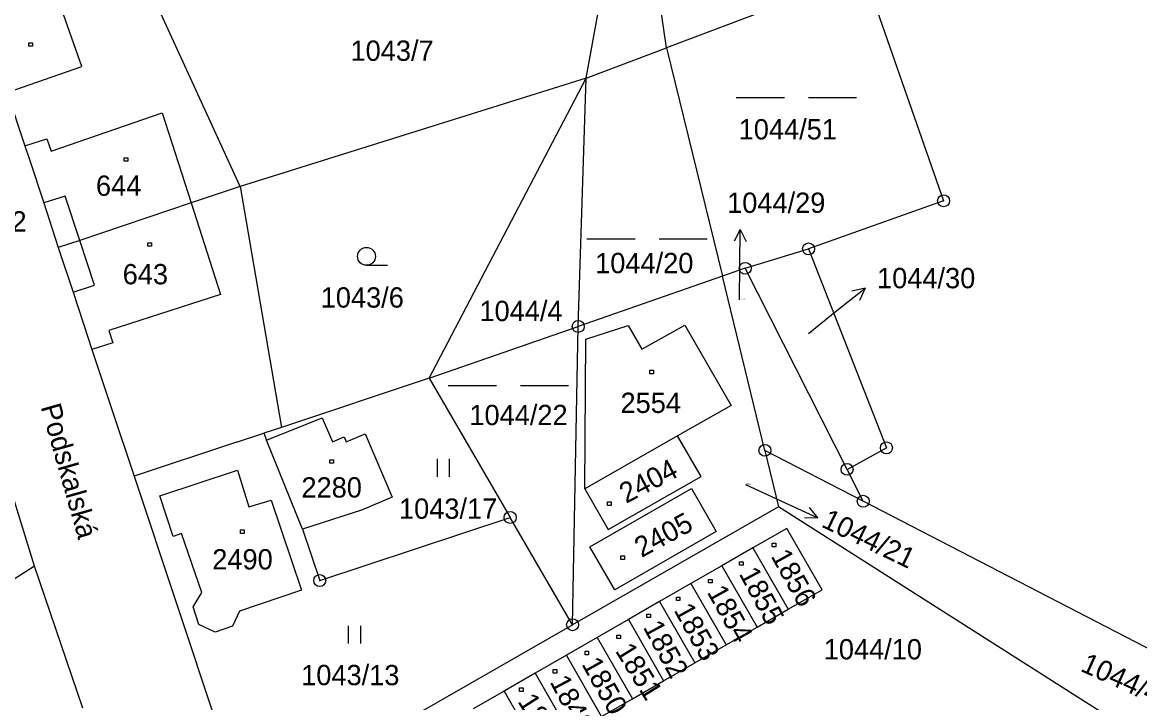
# Model space of a CAD drawing. Extents: x -795483 to -789093, y -1112258 to -1108741.
# Drawn here: x -792126 to -792032.5, y -1109594.4 to -1109537.4 of the extents above; entities that cross this region are included whole.
import ezdxf

# ---------------------------------------------------------------- set-up
doc = ezdxf.new("R2010")
doc.units = 0
for name, color, linetype in [('Komunikace', 7, 'Continuous'), ('Vrstva 1', 7, 'Continuous'), ('Vrstva 14', 7, 'Continuous'), ('Vrstva 15', 7, 'Continuous'), ('Vrstva 16', 7, 'Continuous'), ('Vrstva 2', 7, 'Continuous'), ('Vrstva 23', 7, 'Continuous'), ('Vrstva 25', 7, 'Continuous'), ('Vrstva 28', 7, 'Continuous'), ('Vrstva 38', 7, 'Continuous')]:
    doc.layers.add(name, color=color, linetype=linetype)

msp = doc.modelspace()

# ---------------------------------------------------------------- linework, layer by layer
at = {"layer": 'Komunikace'}
for p, q in [((-792066, -1109560.63), (-792065.97, -1109557.74)), ((-792060.24, -1109563.45), (-792057.85, -1109561.54)), ((-792065.51, -1109576.1), (-792062.18, -1109577.64))]:
    msp.add_line(p, q, dxfattribs=at)
at = {"layer": 'Vrstva 1'}
for p, q in [((-792072.1, -1109539.55), (-792075, -1109519.53)), ((-792078.82, -1109542.08), (-792076.76, -1109530.55)), ((-792107.79, -1109551.14), (-792116.17, -1109532.79)), ((-792055.59, -1109533.29), (-792072.1, -1109539.55)), ((-792055.59, -1109533.29), (-792048.93, -1109552.35)), ((-792078.82, -1109542.08), (-792072.1, -1109539.55)), ((-792072.1, -1109539.55), (-792067.42, -1109558.66)), ((-792078.82, -1109542.08), (-792107.79, -1109551.14)), ((-792091.96, -1109567.21), (-792078.82, -1109542.08)), ((-792079.5, -1109562.87), (-792078.82, -1109542.08)), ((-792127.27, -1109543.27), (-792125.78, -1109547.74)), ((-792125.78, -1109547.74), (-792125.42, -1109548.82)), ((-792125.42, -1109548.82), (-792124.19, -1109552.52)), ((-792107.79, -1109551.14), (-792111.88, -1109552.53)), ((-792107.79, -1109551.14), (-792104.33, -1109571.32)), ((-792048.93, -1109552.35), (-792060.23, -1109556.38)), ((-792124.19, -1109552.52), (-792123, -1109556.27)), ((-792111.88, -1109552.53), (-792121.19, -1109555.68)), ((-792121.19, -1109555.68), (-792123, -1109556.27)), ((-792123, -1109556.27), (-792121.74, -1109560)), ((-792065.53, -1109558), (-792060.23, -1109556.38)), ((-792060.23, -1109556.38), (-792053.71, -1109573.03)), ((-792065.53, -1109558), (-792067.42, -1109558.66)), ((-792057.01, -1109574.83), (-792065.53, -1109558)), ((-792067.42, -1109558.66), (-792079.5, -1109562.87)), ((-792063.88, -1109573.24), (-792067.42, -1109558.66)), ((-792121.74, -1109560), (-792120.53, -1109563.77)), ((-792091.96, -1109567.21), (-792079.5, -1109562.87)), ((-792079.97, -1109587.84), (-792079.5, -1109562.87)), ((-792078.85, -1109563.94), (-792075.31, -1109562.78)), ((-792075.31, -1109562.78), (-792074.18, -1109564.78)), ((-792074.18, -1109564.78), (-792070.57, -1109562.75)), ((-792070.57, -1109562.75), (-792066.71, -1109569.49)), ((-792120.53, -1109563.77), (-792120.18, -1109564.81)), ((-792078.94, -1109576.46), (-792078.85, -1109563.94)), ((-792120.18, -1109564.81), (-792118.56, -1109569.65)), ((-792091.96, -1109567.21), (-792104.33, -1109571.32)), ((-792091.96, -1109567.21), (-792085.19, -1109578.86)), ((-792118.56, -1109569.65), (-792116.64, -1109575.4)), ((-792066.71, -1109569.49), (-792071.18, -1109572.02)), ((-792105.57, -1109572.4), (-792100.91, -1109570.51)), ((-792100.91, -1109570.51), (-792100.05, -1109572.52)), ((-792108.07, -1109572.56), (-792105.81, -1109571.81)), ((-792104.33, -1109571.32), (-792105.81, -1109571.81)), ((-792105.81, -1109571.81), (-792105.57, -1109572.4)), ((-792098.92, -1109572.53), (-792097.31, -1109571.85)), ((-792097.31, -1109571.85), (-792095.07, -1109577.16)), ((-792071.18, -1109572.02), (-792078.94, -1109576.46)), ((-792069.22, -1109575.42), (-792071.18, -1109572.02)), ((-792108.07, -1109572.56), (-792116.64, -1109575.4)), ((-792102.57, -1109579.83), (-792105.57, -1109572.4)), ((-792100.05, -1109572.52), (-792099.09, -1109572.12)), ((-792099.09, -1109572.12), (-792098.92, -1109572.53)), ((-792124.98, -1109582.94), (-792128, -1109573.23)), ((-792063.88, -1109573.24), (-792062.74, -1109577.96)), ((-792055.66, -1109577.5), (-792063.88, -1109573.24)), ((-792057.01, -1109574.83), (-792053.71, -1109573.03)), ((-792055.66, -1109577.5), (-792057.01, -1109574.83)), ((-792116.64, -1109575.4), (-792107.29, -1109603.5)), ((-792114.5, -1109577.06), (-792107.99, -1109574.91)), ((-792107.99, -1109574.91), (-792107.04, -1109577.96)), ((-792076.99, -1109579.86), (-792069.22, -1109575.42)), ((-792078.94, -1109576.46), (-792076.99, -1109579.86)), ((-792078.52, -1109581.31), (-792070.03, -1109576.44)), ((-792070.03, -1109576.44), (-792067.96, -1109580.04)), ((-792113.38, -1109580.46), (-792114.5, -1109577.06)), ((-792107.04, -1109577.96), (-792105.17, -1109577.4)), ((-792105.17, -1109577.4), (-792102.66, -1109584.95)), ((-792095.07, -1109577.16), (-792097.63, -1109578.24)), ((-792019.39, -1109596.27), (-792055.66, -1109577.5)), ((-792097.63, -1109578.24), (-792102.57, -1109579.83)), ((-792062.74, -1109577.96), (-792079.97, -1109587.84)), ((-792030.22, -1109598.67), (-792062.74, -1109577.96)), ((-792101.12, -1109584.14), (-792085.19, -1109578.86)), ((-792079.97, -1109587.84), (-792085.19, -1109578.86)), ((-792112.69, -1109580.19), (-792113.38, -1109580.46)), ((-792110.99, -1109585.13), (-792112.69, -1109580.19)), ((-792102.57, -1109579.83), (-792101.12, -1109584.14)), ((-792067.96, -1109580.04), (-792076.44, -1109584.92)), ((-792062.04, -1109579.77), (-792064.88, -1109581.41)), ((-792059.09, -1109584.91), (-792062.04, -1109579.77)), ((-792076.44, -1109584.92), (-792078.52, -1109581.31)), ((-792064.88, -1109581.41), (-792067.48, -1109582.9)), ((-792064.88, -1109581.41), (-792061.93, -1109586.54)), ((-792124.98, -1109582.94), (-792150.58, -1109599.21)), ((-792120.93, -1109594.82), (-792124.98, -1109582.94)), ((-792067.48, -1109582.9), (-792070.09, -1109584.4)), ((-792067.48, -1109582.9), (-792064.53, -1109588.04)), ((-792111.72, -1109586.33), (-792110.99, -1109585.13)), ((-792102.66, -1109584.95), (-792107.82, -1109586.71)), ((-792070.09, -1109584.4), (-792072.69, -1109585.9)), ((-792070.09, -1109584.4), (-792067.13, -1109589.53)), ((-792061.93, -1109586.54), (-792059.09, -1109584.91)), ((-792072.69, -1109585.9), (-792075.29, -1109587.41)), ((-792072.69, -1109585.9), (-792069.74, -1109591.04)), ((-792111.24, -1109587.81), (-792111.72, -1109586.33)), ((-792107.82, -1109586.71), (-792108.43, -1109587.95)), ((-792064.53, -1109588.04), (-792061.93, -1109586.54)), ((-792109.88, -1109588.45), (-792111.24, -1109587.81)), ((-792108.43, -1109587.95), (-792109.88, -1109588.45)), ((-792095.51, -1109596.74), (-792079.97, -1109587.84)), ((-792075.29, -1109587.41), (-792077.9, -1109588.9)), ((-792075.29, -1109587.41), (-792072.35, -1109592.53)), ((-792077.9, -1109588.9), (-792080.49, -1109590.4)), ((-792077.9, -1109588.9), (-792074.95, -1109594.03)), ((-792067.13, -1109589.53), (-792064.53, -1109588.04)), ((-792069.74, -1109591.04), (-792067.13, -1109589.53)), ((-792080.49, -1109590.4), (-792083.09, -1109591.89)), ((-792077.54, -1109595.52), (-792080.49, -1109590.4)), ((-792072.35, -1109592.53), (-792069.74, -1109591.04)), ((-792083.09, -1109591.89), (-792085.7, -1109593.39)), ((-792083.09, -1109591.89), (-792080.14, -1109597.02)), ((-792074.95, -1109594.03), (-792072.35, -1109592.53)), ((-792085.7, -1109593.39), (-792088.29, -1109594.89)), ((-792085.7, -1109593.39), (-792082.75, -1109598.52)), ((-792077.54, -1109595.52), (-792074.95, -1109594.03))]:
    msp.add_line(p, q, dxfattribs=at)
at = {"layer": 'Vrstva 16'}
for p, q in [((-792065.939, -1109554.74), (-792066.449, -1109555.735)), ((-792065.97, -1109557.74), (-792065.939, -1109554.74)), ((-792065.939, -1109554.74), (-792065.449, -1109555.745)), ((-792057.85, -1109561.54), (-792055.504, -1109559.669)), ((-792055.504, -1109559.669), (-792056.598, -1109559.902)), ((-792055.504, -1109559.669), (-792055.974, -1109560.683)), ((-792062.18, -1109577.64), (-792059.454, -1109578.894)), ((-792059.454, -1109578.894), (-792060.154, -1109578.022)), ((-792059.454, -1109578.894), (-792060.572, -1109578.93))]:
    msp.add_line(p, q, dxfattribs=at)
at = {"layer": 'Vrstva 2'}
for p, q in [((-792121.03, -1109541.11), (-792123.11, -1109535.18)), ((-792127.27, -1109543.27), (-792121.03, -1109541.11)), ((-792123.6, -1109548.19), (-792114.3, -1109544.99)), ((-792114.3, -1109544.99), (-792111.88, -1109552.53)), ((-792125.78, -1109547.74), (-792123.96, -1109547.16)), ((-792123.96, -1109547.16), (-792123.6, -1109548.19)), ((-792122.41, -1109551.96), (-792124.19, -1109552.52)), ((-792121.19, -1109555.68), (-792122.41, -1109551.96)), ((-792111.88, -1109552.53), (-792109.42, -1109560.18)), ((-792119.97, -1109559.4), (-792121.19, -1109555.68)), ((-792121.74, -1109560), (-792119.97, -1109559.4)), ((-792109.42, -1109560.18), (-792118.76, -1109563.2)), ((-792118.76, -1109563.2), (-792118.43, -1109564.23)), ((-792118.43, -1109564.23), (-792120.18, -1109564.81))]:
    msp.add_line(p, q, dxfattribs=at)
at = {"layer": 'Vrstva 23'}
for p, q in [((-792066.275, -1109543.7), (-792062.255, -1109543.7)), ((-792060.245, -1109543.7), (-792056.225, -1109543.7)), ((-792078.765, -1109555.52), (-792074.745, -1109555.52)), ((-792072.735, -1109555.52), (-792068.715, -1109555.52)), ((-792097.21, -1109557.75), (-792095.46, -1109557.75)), ((-792090.365, -1109567.8), (-792086.345, -1109567.8)), ((-792084.335, -1109567.8), (-792080.315, -1109567.8)), ((-792091.28, -1109575.46), (-792091.28, -1109573.96)), ((-792090.28, -1109573.96), (-792090.28, -1109575.46)), ((-792098.71, -1109589.42), (-792098.71, -1109587.92)), ((-792097.71, -1109587.92), (-792097.71, -1109589.42))]:
    msp.add_line(p, q, dxfattribs=at)
msp.add_circle((-792097.21, -1109557), 0.75, dxfattribs=at)
at = {"layer": 'Vrstva 25'}
for p, q in [((-792125.45, -1109539.11), (-792125.15, -1109539.11)), ((-792125.45, -1109539.41), (-792125.45, -1109539.11)), ((-792125.15, -1109539.11), (-792125.15, -1109539.41)), ((-792125.15, -1109539.41), (-792125.45, -1109539.41)), ((-792117.47, -1109548.74), (-792117.17, -1109548.74)), ((-792117.47, -1109549.04), (-792117.47, -1109548.74)), ((-792117.17, -1109549.04), (-792117.47, -1109549.04)), ((-792117.17, -1109548.74), (-792117.17, -1109549.04)), ((-792115.49, -1109555.86), (-792115.19, -1109555.86)), ((-792115.49, -1109556.16), (-792115.49, -1109555.86)), ((-792115.19, -1109556.16), (-792115.49, -1109556.16)), ((-792115.19, -1109555.86), (-792115.19, -1109556.16)), ((-792073.5, -1109566.54), (-792073.2, -1109566.54)), ((-792073.5, -1109566.84), (-792073.5, -1109566.54)), ((-792073.2, -1109566.84), (-792073.5, -1109566.84)), ((-792073.2, -1109566.54), (-792073.2, -1109566.84)), ((-792100.28, -1109574.02), (-792099.98, -1109574.02)), ((-792100.28, -1109574.32), (-792100.28, -1109574.02)), ((-792099.98, -1109574.32), (-792100.28, -1109574.32)), ((-792099.98, -1109574.02), (-792099.98, -1109574.32)), ((-792077.05, -1109577.55), (-792076.75, -1109577.55)), ((-792077.05, -1109577.85), (-792077.05, -1109577.55)), ((-792076.75, -1109577.55), (-792076.75, -1109577.85)), ((-792076.75, -1109577.85), (-792077.05, -1109577.85)), ((-792107.74, -1109579.9), (-792107.44, -1109579.9)), ((-792107.74, -1109580.2), (-792107.74, -1109579.9)), ((-792107.44, -1109580.2), (-792107.74, -1109580.2)), ((-792107.44, -1109579.9), (-792107.44, -1109580.2)), ((-792063.28, -1109581.02), (-792062.98, -1109581.02)), ((-792063.28, -1109581.32), (-792063.28, -1109581.02)), ((-792062.98, -1109581.32), (-792063.28, -1109581.32)), ((-792062.98, -1109581.02), (-792062.98, -1109581.32)), ((-792075.94, -1109582.08), (-792075.64, -1109582.08)), ((-792075.94, -1109582.38), (-792075.94, -1109582.08)), ((-792075.64, -1109582.08), (-792075.64, -1109582.38)), ((-792075.64, -1109582.38), (-792075.94, -1109582.38)), ((-792066, -1109582.56), (-792065.7, -1109582.56)), ((-792066, -1109582.86), (-792066, -1109582.56)), ((-792065.7, -1109582.86), (-792066, -1109582.86)), ((-792065.7, -1109582.56), (-792065.7, -1109582.86)), ((-792068.59, -1109584.04), (-792068.29, -1109584.04)), ((-792068.59, -1109584.34), (-792068.59, -1109584.04)), ((-792068.29, -1109584.04), (-792068.29, -1109584.34)), ((-792068.29, -1109584.34), (-792068.59, -1109584.34)), ((-792071.29, -1109585.52), (-792070.99, -1109585.52)), ((-792071.29, -1109585.82), (-792071.29, -1109585.52)), ((-792070.99, -1109585.82), (-792071.29, -1109585.82)), ((-792070.99, -1109585.52), (-792070.99, -1109585.82)), ((-792073.75, -1109586.94), (-792073.45, -1109586.94)), ((-792073.75, -1109587.24), (-792073.75, -1109586.94)), ((-792073.45, -1109586.94), (-792073.45, -1109587.24)), ((-792073.45, -1109587.24), (-792073.75, -1109587.24)), ((-792076.26, -1109588.7), (-792075.96, -1109588.7)), ((-792076.26, -1109589), (-792076.26, -1109588.7)), ((-792075.96, -1109588.7), (-792075.96, -1109589)), ((-792075.96, -1109589), (-792076.26, -1109589)), ((-792078.93, -1109590.06), (-792078.63, -1109590.06)), ((-792078.93, -1109590.36), (-792078.93, -1109590.06)), ((-792078.63, -1109590.36), (-792078.93, -1109590.36)), ((-792078.63, -1109590.06), (-792078.63, -1109590.36)), ((-792081.59, -1109591.59), (-792081.29, -1109591.59)), ((-792081.59, -1109591.89), (-792081.59, -1109591.59)), ((-792081.29, -1109591.59), (-792081.29, -1109591.89)), ((-792081.29, -1109591.89), (-792081.59, -1109591.89)), ((-792084.4, -1109593.13), (-792084.1, -1109593.13)), ((-792084.4, -1109593.43), (-792084.4, -1109593.13)), ((-792084.1, -1109593.43), (-792084.4, -1109593.43)), ((-792084.1, -1109593.13), (-792084.1, -1109593.43))]:
    msp.add_line(p, q, dxfattribs=at)
at = {"layer": 'Vrstva 28'}
for centre, radius in [((-792048.93, -1109552.35), 0.5), ((-792048.93, -1109552.35), 0.01), ((-792060.23, -1109556.38), 0.5), ((-792060.23, -1109556.38), 0.01), ((-792065.53, -1109558), 0.5), ((-792065.53, -1109558), 0.01), ((-792079.5, -1109562.87), 0.5), ((-792079.5, -1109562.87), 0.01), ((-792063.88, -1109573.24), 0.5), ((-792053.71, -1109573.03), 0.5), ((-792063.88, -1109573.24), 0.01), ((-792053.71, -1109573.03), 0.01), ((-792057.01, -1109574.83), 0.5), ((-792057.01, -1109574.83), 0.01), ((-792055.66, -1109577.5), 0.5), ((-792055.66, -1109577.5), 0.01), ((-792085.19, -1109578.86), 0.5), ((-792085.19, -1109578.86), 0.01), ((-792101.12, -1109584.14), 0.5), ((-792101.12, -1109584.14), 0.01), ((-792079.97, -1109587.84), 0.5), ((-792079.97, -1109587.84), 0.01)]:
    msp.add_circle(centre, radius, dxfattribs=at)

# ---------------------------------------------------------------- texts
at = {"layer": 'Vrstva 14'}
for s, height, p in [('1043/7', 1.7, (-792098.545, -1109540.63)), ('1044/51', 1.7, (-792066.073, -1109547.21)), ('1043/12', 1.7, (-792133.861, -1109554.92)), ('1044/20', 1.7, (-792078.08, -1109558.41)), ('1043/6', 1.7, (-792101.038, -1109561.29)), ('1044/4', 1.7, (-792087.76, -1109562.42)), ('1044/29', 0.1, (-792066, -1109560.63)), ('1044/30', 0.1, (-792060.24, -1109563.45)), ('1044/22', 1.7, (-792088.6, -1109571.13)), ('1044/21', 0.1, (-792065.51, -1109576.1)), ('1043/17', 1.7, (-792094.49, -1109578.97)), ('1044/10', 1.7, (-792058.96, -1109590.74)), ('1043/13', 1.7, (-792102.671, -1109592.9))]:
    msp.add_text(s, height=height, dxfattribs=at).set_placement(p)
msp.add_text('1044/45', height=1.7, rotation=335.7, dxfattribs=at).set_placement((-792037.566, -1109591.68))
at = {"layer": 'Vrstva 15'}
for s, p in [('644', (-792119.838, -1109551.93)), ('643', (-792117.603, -1109559.34)), ('2554', (-792075.96, -1109570.11)), ('2280', (-792102.65, -1109577.19)), ('2490', (-792110.11, -1109583.21))]:
    msp.add_text(s, height=1.7, dxfattribs=at).set_placement(p)
for s, rotation, p in [('2404', 27.62343, (-792075.49, -1109577.72)), ('2405', 28.30752, (-792074.2, -1109582.25)), ('1856', 299.10897, (-792063.42, -1109582.09)), ('1855', 298.26855, (-792066.08, -1109583.57)), ('1854', 299.23281, (-792068.76, -1109585.11)), ('1853', 299.14974, (-792071.54, -1109586.61)), ('1852', 298.46808, (-792074.11, -1109588.04)), ('1851', 301.75245, (-792076.45, -1109590.02)), ('1850', 299.19753, (-792079.25, -1109591.13)), ('1849', 297.99414, (-792081.91, -1109592.61)), ('1848', 302.45922, (-792084.61, -1109594.26))]:
    msp.add_text(s, height=1.7, rotation=rotation, dxfattribs=at).set_placement(p)
at = {"layer": 'Vrstva 16'}
for s, p in [('1044/29', (-792067.04, -1109553.36)), ('1044/30', (-792054.5, -1109559.67))]:
    msp.add_text(s, height=1.7, dxfattribs=at).set_placement(p)
msp.add_text('1044/21', height=1.7, rotation=334.15965, dxfattribs=at).set_placement((-792059.24, -1109579.6))
at = {"layer": 'Vrstva 38'}
msp.add_text('Podskalská', height=1.7, rotation=285.86493, dxfattribs=at).set_placement((-792124.48, -1109569.59))

doc.saveas('drawing.dxf')
